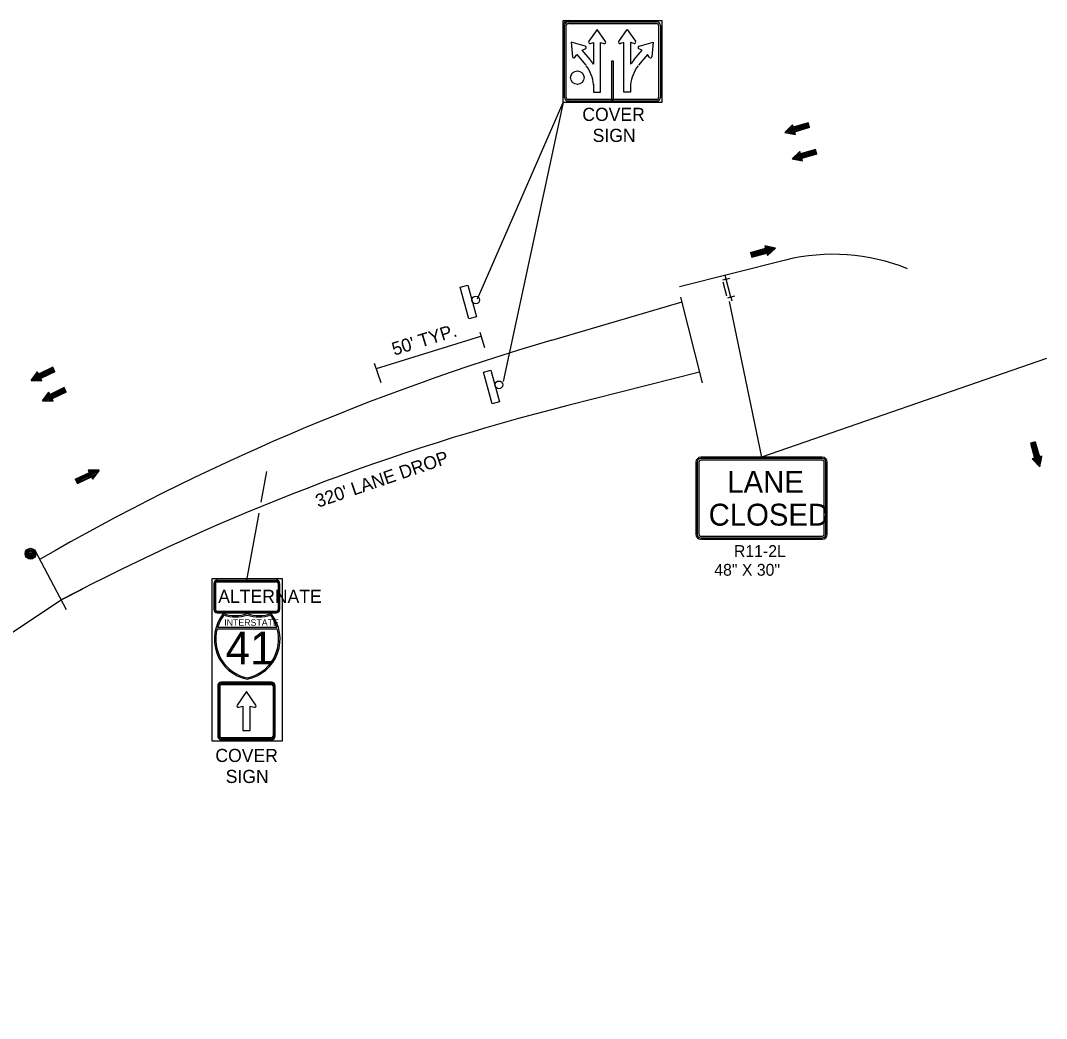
# Model space of a CAD drawing. Extents: x 358662 to 361839, y 132407 to 133741.
# Drawn here: x 360084 to 360552.6, y 132954.4 to 133410.3 of the extents above; entities that cross this region are included whole.
import ezdxf

# ---------------------------------------------------------------- set-up
doc = ezdxf.new("R2010")
doc.units = 0
for name, color, linetype in [('E_BLD_Dash', 7, 'Continuous'), ('E_BLD_Footing', 7, 'Continuous'), ('E_BLD_Name', 7, 'Continuous'), ('E_DTM_RandomShots', 7, 'Continuous'), ('E_MISCPROP_ShtDash', 7, 'Continuous'), ('E_WTR_Wetland', 7, 'Continuous'), ('P_FTMS_LaneLbl', 7, 'Continuous')]:
    doc.layers.add(name, color=color, linetype=linetype)

msp = doc.modelspace()

# ---------------------------------------------------------------- linework, layer by layer
at = {"layer": 'E_BLD_Dash'}
for p, q in [((360406.37, 133292.17), (360405.94, 133293.81)), ((360406.37, 133292.17), (360408.02, 133292.6)), ((360406.37, 133292.17), (360404.73, 133291.74)), ((360406.63, 133284.48), (360404.98, 133290.77)), ((360408.53, 133283.94), (360406.37, 133292.17)), ((360408.53, 133283.94), (360406.88, 133283.51)), ((360410.17, 133284.37), (360408.53, 133283.94)), ((360408.53, 133283.94), (360408.96, 133282.3))]:
    msp.add_line(p, q, dxfattribs=at)
for radius in [2.5, 2, 1.5, 1, 0.5, 0.25]:
    msp.add_circle((360088.6, 133166.72), radius, dxfattribs=at)
at = {"layer": 'E_BLD_Footing'}
for p, q in [((360433.11, 133359.19), (360436.68, 133362.62)), ((360444.09, 133362.68), (360433.51, 133359.58)), ((360443.96, 133363.11), (360434.22, 133360.26)), ((360437.95, 133358.3), (360436.68, 133362.62)), ((360443.84, 133363.54), (360437, 133361.54)), ((360444.47, 133361.38), (360443.84, 133363.54)), ((360433.11, 133359.19), (360437.95, 133358.3)), ((360444.22, 133362.25), (360433.52, 133359.12)), ((360444.34, 133361.81), (360434.51, 133358.94)), ((360436.98, 133361.53), (360434.92, 133360.93)), ((360437.61, 133359.37), (360435.49, 133358.76)), ((360436.85, 133361.97), (360435.63, 133361.61)), ((360436.72, 133362.4), (360436.33, 133362.28)), ((360437.73, 133358.94), (360436.47, 133358.57)), ((360437.86, 133358.51), (360437.45, 133358.39)), ((360444.47, 133361.38), (360437.63, 133359.38)), ((360444.15, 133362.46), (360444.15, 133362.46)), ((360436.44, 133347.11), (360440.01, 133350.54)), ((360447.42, 133350.59), (360436.84, 133347.5)), ((360447.55, 133350.16), (360436.86, 133347.03)), ((360447.29, 133351.03), (360437.55, 133348.17)), ((360447.67, 133349.73), (360437.84, 133346.85)), ((360440.31, 133349.45), (360438.25, 133348.85)), ((360440.18, 133349.88), (360438.96, 133349.52)), ((360440.05, 133350.31), (360439.66, 133350.2)), ((360441.28, 133346.22), (360440.01, 133350.54)), ((360447.17, 133351.46), (360440.33, 133349.46)), ((360447.8, 133349.3), (360440.97, 133347.3)), ((360447.8, 133349.3), (360447.17, 133351.46)), ((360447.48, 133350.38), (360447.48, 133350.38)), ((360436.44, 133347.11), (360441.28, 133346.22)), ((360440.94, 133347.29), (360438.82, 133346.67)), ((360441.07, 133346.86), (360439.8, 133346.49)), ((360441.19, 133346.43), (360440.79, 133346.31)), ((360417.57, 133303.97), (360427.46, 133306.63)), ((360417.68, 133303.54), (360428.44, 133306.43)), ((360428.86, 133306.35), (360424.04, 133307.34)), ((360424.04, 133307.34), (360425.21, 133303)), ((360424.12, 133307.13), (360424.53, 133307.24)), ((360424.24, 133306.7), (360425.5, 133307.04)), ((360424.35, 133306.26), (360426.48, 133306.84)), ((360428.86, 133306.35), (360425.21, 133303)), ((360417.45, 133304.4), (360424.33, 133306.26)), ((360417.45, 133304.4), (360418.03, 133302.23)), ((360417.74, 133303.32), (360417.74, 133303.32)), ((360417.8, 133303.1), (360428.44, 133305.97)), ((360417.92, 133302.67), (360427.72, 133305.31)), ((360418.03, 133302.23), (360424.91, 133304.08)), ((360424.94, 133304.09), (360427, 133304.65)), ((360425.05, 133303.66), (360426.29, 133303.99)), ((360425.17, 133303.22), (360425.57, 133303.33)), ((360099.14, 133251.1), (360089.22, 133246.3)), ((360099.33, 133250.7), (360089.31, 133245.84)), ((360098.94, 133251.51), (360089.8, 133247.08)), ((360099.53, 133250.29), (360090.31, 133245.83)), ((360098.75, 133251.91), (360092.33, 133248.81)), ((360099.73, 133249.89), (360098.75, 133251.91)), ((360099.24, 133250.9), (360099.24, 133250.9)), ((360088.88, 133245.85), (360091.84, 133249.82)), ((360088.88, 133245.85), (360093.8, 133245.77)), ((360092.31, 133248.8), (360090.38, 133247.86)), ((360092.12, 133249.2), (360090.97, 133248.65)), ((360093.29, 133246.77), (360091.31, 133245.81)), ((360091.92, 133249.61), (360091.55, 133249.43)), ((360093.8, 133245.77), (360091.84, 133249.82)), ((360093.49, 133246.37), (360092.3, 133245.79)), ((360093.68, 133245.96), (360093.3, 133245.78)), ((360099.73, 133249.89), (360093.32, 133246.78)), ((360104.33, 133241.8), (360094.41, 133237)), ((360104.53, 133241.39), (360094.5, 133236.54)), ((360104.13, 133242.2), (360095, 133237.78)), ((360104.72, 133240.99), (360095.5, 133236.52)), ((360103.94, 133242.61), (360097.53, 133239.51)), ((360104.92, 133240.58), (360103.94, 133242.61)), ((360104.43, 133241.6), (360104.43, 133241.6)), ((360094.08, 133236.55), (360097.03, 133240.52)), ((360094.08, 133236.55), (360099, 133236.47)), ((360097.5, 133239.49), (360095.58, 133238.56)), ((360097.31, 133239.9), (360096.16, 133239.34)), ((360098.48, 133237.47), (360096.5, 133236.51)), ((360097.11, 133240.3), (360096.74, 133240.12)), ((360099, 133236.47), (360097.03, 133240.52)), ((360098.68, 133237.06), (360097.5, 133236.49)), ((360098.88, 133236.66), (360098.5, 133236.47)), ((360104.92, 133240.58), (360098.51, 133237.48)), ((360547.46, 133217.83), (360545.29, 133217.21)), ((360545.73, 133217.33), (360548.5, 133207.57)), ((360546.16, 133217.46), (360549.17, 133206.86)), ((360546.38, 133217.52), (360546.38, 133217.52)), ((360546.59, 133217.58), (360549.64, 133206.86)), ((360547.03, 133217.7), (360549.82, 133207.85)), ((360547.46, 133217.83), (360549.4, 133210.98)), ((360545.29, 133217.21), (360547.24, 133210.36)), ((360550.49, 133211.28), (360546.16, 133210.05)), ((360549.55, 133206.45), (360546.16, 133210.05)), ((360546.38, 133210.09), (360546.49, 133209.69)), ((360546.81, 133210.21), (360547.16, 133208.99)), ((360547.25, 133210.34), (360547.83, 133208.28)), ((360549.41, 133210.95), (360550.01, 133208.83)), ((360549.55, 133206.45), (360550.49, 133211.28)), ((360549.84, 133211.07), (360550.2, 133209.81)), ((360550.28, 133211.2), (360550.39, 133210.79)), ((360109.07, 133200.81), (360115.48, 133203.91)), ((360109.27, 133200.41), (360118.49, 133204.87)), ((360109.46, 133200), (360119.49, 133204.86)), ((360109.66, 133199.6), (360119.58, 133204.4)), ((360109.86, 133199.19), (360119, 133203.62)), ((360119.91, 133204.85), (360114.99, 133204.93)), ((360114.99, 133204.93), (360116.96, 133200.88)), ((360115.11, 133204.74), (360115.49, 133204.92)), ((360115.31, 133204.33), (360116.49, 133204.9)), ((360115.51, 133203.93), (360117.49, 133204.89)), ((360119.91, 133204.85), (360116.96, 133200.88)), ((360109.07, 133200.81), (360110.05, 133198.79)), ((360109.56, 133199.8), (360109.56, 133199.8)), ((360110.05, 133198.79), (360116.46, 133201.89)), ((360116.49, 133201.9), (360118.41, 133202.83)), ((360116.68, 133201.5), (360117.83, 133202.05)), ((360116.88, 133201.09), (360117.25, 133201.27))]:
    msp.add_line(p, q, dxfattribs=at)
at = {"layer": 'E_BLD_Name'}
msp.add_lwpolyline([(360326.79, 133264.31), (360326.79, 133264.31), (360386.32, 133281.76)], dxfattribs=at)
msp.add_arc((360629.58, 132233.23), 1074.62, 106.36577, 119.95236, dxfattribs=at)
at = {"layer": 'E_DTM_RandomShots'}
msp.add_line((360433.5, 133300.92), (360385.03, 133288.65), dxfattribs=at)
msp.add_arc((360455.13, 133212.84), 90.69, 68.0067, 103.7932, dxfattribs=at)
at = {"layer": 'E_MISCPROP_ShtDash'}
for p, q in [((360392.5, 133208.51), (360392.5, 133175.68)), ((360393.12, 133208.51), (360393.12, 133175.68)), ((360393.91, 133208.49), (360393.91, 133175.68)), ((360450.17, 133210.85), (360394.84, 133210.85)), ((360450.17, 133210.23), (360394.84, 133210.23)), ((360450.17, 133209.45), (360394.84, 133209.45)), ((360451.11, 133175.68), (360451.11, 133208.51)), ((360451.89, 133175.68), (360451.89, 133208.51)), ((360452.52, 133175.68), (360452.52, 133208.51)), ((360394.84, 133174.75), (360450.17, 133174.75)), ((360394.84, 133173.97), (360450.17, 133173.97)), ((360394.84, 133173.34), (360450.17, 133173.34))]:
    msp.add_line(p, q, dxfattribs=at)
for centre, radius, start, end in [((360394.84, 133208.51), 2.34, 90, 180), ((360394.84, 133208.51), 1.72, 90, 180), ((360394.84, 133208.51), 0.938, 90, 181.0779), ((360450.17, 133208.51), 2.34, 0, 90), ((360450.17, 133208.51), 1.72, 0, 90), ((360450.17, 133208.51), 0.938, 0, 90), ((360394.84, 133175.68), 2.34, 180, 270), ((360394.84, 133175.68), 1.72, 180, 270), ((360394.84, 133175.68), 0.938, 180, 270), ((360450.17, 133175.68), 0.938, 270, 360), ((360450.17, 133175.68), 1.72, 270, 360), ((360450.17, 133175.68), 2.34, 270, 360)]:
    msp.add_arc(centre, radius, start, end, dxfattribs=at)
at = {"layer": 'E_WTR_Wetland'}
for p, q in [((360331.91, 133372.83), (360331.91, 133410.33)), ((360331.91, 133410.33), (360376.91, 133410.33)), ((360376.91, 133410.33), (360376.91, 133372.83)), ((360347.38, 133406.26), (360343.59, 133400.84)), ((360351.21, 133400.8), (360347.38, 133406.26)), ((360357.33, 133400.8), (360361.16, 133406.26)), ((360361.16, 133406.26), (360364.96, 133400.84)), ((360341.99, 133398.66), (360335.54, 133400.39)), ((360335.54, 133400.39), (360336.12, 133393.79)), ((360344.27, 133399.88), (360345.82, 133400.33)), ((360345.82, 133400.33), (360345.82, 133390.35)), ((360348.94, 133377.61), (360348.94, 133400.32)), ((360348.94, 133400.32), (360350.46, 133399.86)), ((360359.6, 133400.32), (360358.09, 133399.86)), ((360359.6, 133377.61), (360359.6, 133400.32)), ((360364.27, 133399.88), (360362.72, 133400.33)), ((360362.72, 133400.33), (360362.72, 133390.35)), ((360366.55, 133398.66), (360373, 133400.39)), ((360373, 133400.39), (360372.43, 133393.79)), ((360340.55, 133396.84), (360342.01, 133397.46)), ((360344.24, 133392.45), (360340.55, 133396.84)), ((360364.31, 133392.45), (360367.99, 133396.84)), ((360367.99, 133396.84), (360366.53, 133397.46)), ((360337.26, 133393.5), (360338.16, 133394.84)), ((360338.16, 133394.84), (360342.27, 133389.93)), ((360370.39, 133394.84), (360366.27, 133389.93)), ((360371.28, 133393.5), (360370.39, 133394.84)), ((360345.82, 133381.25), (360345.82, 133377.61)), ((360345.82, 133377.61), (360348.94, 133377.61)), ((360362.72, 133377.61), (360359.6, 133377.61)), ((360362.72, 133381.25), (360362.72, 133377.61)), ((360376.91, 133372.83), (360331.91, 133372.83)), ((360354.02, 133374.23), (360354.8, 133374.23)), ((360172.4, 133153.22), (360172.4, 133141.22)), ((360172.77, 133153.22), (360172.77, 133141.22)), ((360173.15, 133153.22), (360173.15, 133141.22)), ((360173.9, 133154.72), (360200.9, 133154.72)), ((360173.9, 133154.34), (360200.9, 133154.34)), ((360173.9, 133153.97), (360200.9, 133153.97)), ((360201.65, 133153.22), (360201.65, 133141.22)), ((360202.02, 133153.22), (360202.02, 133141.22)), ((360202.4, 133153.22), (360202.4, 133141.22)), ((360173.9, 133140.47), (360200.9, 133140.47)), ((360173.9, 133140.09), (360200.9, 133140.09)), ((360173.9, 133139.72), (360200.9, 133139.72)), ((360201.14, 133133.12), (360174.02, 133133.12)), ((360173.84, 133132.5), (360201.32, 133132.5)), ((360174.11, 133106.4), (360174.11, 133083.43)), ((360174.55, 133106.4), (360174.55, 133083.43)), ((360175.09, 133106.4), (360175.09, 133083.43)), ((360198.72, 133108.04), (360175.75, 133108.04)), ((360175.75, 133107.61), (360198.72, 133107.61)), ((360175.75, 133107.06), (360198.72, 133107.06)), ((360199.37, 133106.4), (360199.37, 133083.43)), ((360199.92, 133106.4), (360199.92, 133083.43)), ((360200.36, 133083.43), (360200.36, 133106.4)), ((360187.23, 133103.78), (360182.97, 133097.59)), ((360191.49, 133097.59), (360187.23, 133103.78)), ((360183.7, 133096.59), (360185.59, 133097.16)), ((360185.59, 133097.16), (360185.59, 133085.95)), ((360188.87, 133085.95), (360188.87, 133097.16)), ((360188.87, 133097.16), (360190.76, 133096.59)), ((360175.75, 133082.78), (360198.72, 133082.78)), ((360175.75, 133082.23), (360198.72, 133082.23)), ((360175.75, 133081.79), (360198.72, 133081.79)), ((360185.59, 133085.95), (360188.87, 133085.95))]:
    msp.add_line(p, q, dxfattribs=at)
for points in [[(360334.26, 133409.7), (360374.57, 133409.7)], [(360332.54, 133375.17), (360332.54, 133407.98)], [(360333.32, 133375.15), (360333.32, 133408.01)], [(360334.28, 133408.92), (360374.65, 133408.92)], [(360375.51, 133408.06), (360375.51, 133375.06)], [(360376.29, 133407.98), (360376.29, 133375.17)], [(360354.81, 133374.23), (360354.81, 133391.73), (360354.02, 133391.73), (360354.02, 133374.23)], [(360354.07, 133390.05), (360354.07, 133390.05)], [(360354.85, 133390.05), (360354.85, 133390.05)], [(360354.02, 133374.23), (360334.23, 133374.23)], [(360374.57, 133373.45), (360334.26, 133373.45)], [(360354.81, 133374.23), (360354.8, 133374.23)], [(360374.68, 133374.23), (360354.81, 133374.23)]]:
    msp.add_lwpolyline(points, dxfattribs=at)
for points in [[(360292.24, 133274.96), (360288.86, 133274.04), (360284.92, 133288.51), (360288.3, 133289.43)], [(360302.81, 133236.19), (360299.43, 133235.27), (360295.49, 133249.75), (360298.86, 133250.67)]]:
    msp.add_lwpolyline(points, close=True, dxfattribs=at)
for centre, radius in [((360338.38, 133384.22), 3.09), ((360291.96, 133282.66), 1.75), ((360302.52, 133243.89), 1.75)]:
    msp.add_circle(centre, radius, dxfattribs=at)
for centre, radius, start, end in [((360334.26, 133407.98), 2.34, 90, 180), ((360334.26, 133407.98), 1.72, 90, 180), ((360374.57, 133407.98), 1.72, 0, 90), ((360334.26, 133407.98), 0.938, 88.8766, 180), ((360374.57, 133407.98), 0.938, 0, 90), ((360344.1, 133400.48), 0.625, 145.0012, 286.1627), ((360350.7, 133400.44), 0.625, 247.1433, 34.9993), ((360357.84, 133400.44), 0.625, 145.0007, 292.8567), ((360364.44, 133400.48), 0.625, 253.8373, 34.9988), ((360341.82, 133398.05), 0.625, 287.1813, 74.9736), ((360366.72, 133398.05), 0.625, 105.0264, 252.8187), ((360336.74, 133393.85), 0.625, 184.9754, 326.137), ((360329.32, 133379.54), 19.72, 33.2334, 41.2419), ((360379.22, 133379.54), 19.72, 138.7581, 146.7666), ((360371.8, 133393.85), 0.625, 213.863, 355.0246), ((360329.32, 133379.54), 16.56, 5.0593, 37.5763), ((360379.22, 133379.54), 16.56, 142.4237, 174.9407), ((360334.26, 133375.17), 1.72, 180, 270), ((360334.26, 133375.17), 0.938, 180, 270), ((360374.57, 133375.17), 1.72, 270, 360), ((360374.57, 133375.17), 0.938, 270, 360), ((360173.9, 133153.22), 1.5, 90, 180), ((360173.9, 133153.22), 1.13, 90, 180), ((360173.9, 133153.22), 0.75, 90, 180), ((360200.9, 133153.22), 1.5, 0, 90), ((360200.9, 133153.22), 1.13, 0, 90), ((360200.9, 133153.22), 0.75, 0, 90), ((360173.9, 133141.22), 1.5, 180, 270), ((360191.33, 133127.75), 18.75, 141.669, 258.463), ((360173.9, 133141.22), 1.13, 180, 270), ((360173.9, 133141.22), 0.75, 180, 270), ((360191.33, 133127.75), 18.12, 143.0041, 162.745), ((360182.1, 133157.3), 18.75, 253.004, 286.991), ((360182.1, 133157.3), 19.37, 254.2877, 286.4271), ((360183.83, 133127.75), 18.75, 281.537, 38.331), ((360193.06, 133157.3), 18.75, 253.009, 286.996), ((360193.06, 133157.3), 19.37, 253.5729, 285.7123), ((360183.83, 133127.75), 18.12, 17.255, 36.9959), ((360200.9, 133141.22), 1.5, 270, 360), ((360200.9, 133141.22), 1.13, 270, 360), ((360200.9, 133141.22), 0.75, 270, 360), ((360191.33, 133127.75), 18.12, 164.8028, 258.0595), ((360183.83, 133127.75), 18.12, 281.9405, 15.1972), ((360175.75, 133106.4), 1.64, 90, 180), ((360175.75, 133106.4), 1.2, 90, 180), ((360175.75, 133106.4), 0.656, 90, 180), ((360198.72, 133106.4), 1.64, 60.6035, 90), ((360198.72, 133106.4), 1.64, 0, 90), ((360198.72, 133106.4), 1.2, 0, 90), ((360198.72, 133106.4), 0.656, 0, 90), ((360183.51, 133097.21), 0.656, 145.4703, 286.8026), ((360190.95, 133097.21), 0.656, 253.1974, 34.5297), ((360175.75, 133083.43), 1.64, 180, 270), ((360175.75, 133083.43), 1.2, 180, 270), ((360175.75, 133083.43), 0.656, 180, 270), ((360198.72, 133083.43), 1.2, 270, 0), ((360198.72, 133083.43), 1.64, 270, 0), ((360198.72, 133083.43), 0.656, 270, 0)]:
    msp.add_arc(centre, radius, start, end, dxfattribs=at)
at = {"layer": 'P_FTMS_LaneLbl'}
for p, q in [((360292.73, 133283.22), (360331.91, 133372.83)), ((360331.91, 133372.83), (360304.53, 133245.36)), ((360385.5, 133283.93), (360395.4, 133244.85)), ((360407.64, 133281.97), (360422.51, 133210.85)), ((360246.57, 133251.3), (360294.36, 133266.16)), ((360296.06, 133260.79), (360294.01, 133267.77)), ((360552.64, 133255.89), (360422.51, 133210.85)), ((360248.81, 133244.77), (360245.76, 133253.65)), ((360394.17, 133249.7), (360334.07, 133234.48)), ((360193.93, 133190.35), (360196.49, 133204.29)), ((360187.4, 133154.72), (360192.99, 133185.22)), ((360090.58, 133168.44), (360104.94, 133141.2)), ((360102.61, 133145.62), (360112.5, 133150.77)), ((359812.42, 132954.44), (360102.61, 133145.62))]:
    msp.add_line(p, q, dxfattribs=at)
for points in [[(360331.91, 133410.33), (360376.91, 133410.33), (360376.91, 133372.83), (360331.91, 133372.83)], [(360171.53, 133155.42), (360203.61, 133155.42), (360203.61, 133081.07), (360171.53, 133081.07)]]:
    msp.add_lwpolyline(points, close=True, dxfattribs=at)
msp.add_arc((360591.3, 132218.54), 1048, 104.20848, 117.79516, dxfattribs=at)

# ---------------------------------------------------------------- texts
at = {"layer": 'E_MISCPROP_ShtDash'}
for s, height, p in [('LANE', 10, (360406.86, 133194.6)), ('CLOSED', 10, (360398.35, 133179.59)), ('R11-2L', 5.4, (360409.89, 133165.27)), ('48" X 30"', 5.4, (360400.92, 133156.7))]:
    msp.add_text(s, height=height, dxfattribs=at).set_placement(p)
at = {"layer": 'E_WTR_Wetland'}
for s, height, p in [('ALTERNATE', 6, (360174.37, 133144.28)), ('INTERSTATE', 3, (360177.08, 133133.82)), ('41', 15, (360177.75, 133116.17))]:
    msp.add_text(s, height=height, dxfattribs=at).set_placement(p)
at = {"layer": 'P_FTMS_LaneLbl'}
for s, p in [('COVER', (360340.65, 133364.45)), ('SIGN', (360345.37, 133354.85)), ('COVER', (360173.05, 133071.61)), ('SIGN', (360177.77, 133062.01))]:
    msp.add_text(s, height=6, dxfattribs=at).set_placement(p)
for s, rotation, p in [("50' TYP.", 17.1472, (360254.74, 133257.2)), ("320' LANE DROP", 18.8112, (360220, 133187.74))]:
    msp.add_text(s, height=6, rotation=rotation, dxfattribs=at).set_placement(p)

doc.saveas('drawing.dxf')
